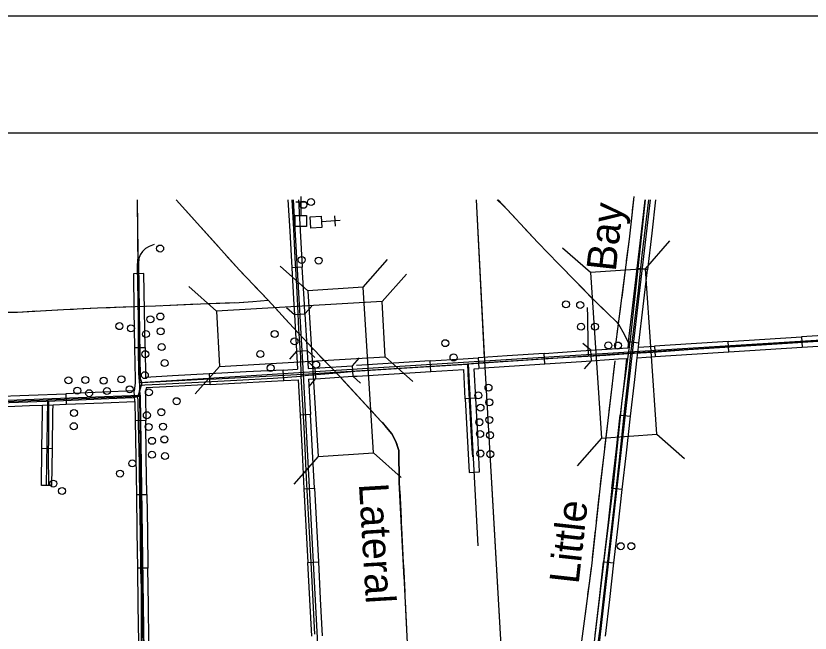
# Model space of a CAD drawing. Extents: x 646058 to 725608, y 1473014 to 1561048.
# Drawn here: x 656968 to 662655, y 1556632 to 1561048 of the extents above; entities that cross this region are included whole.
import ezdxf

# ---------------------------------------------------------------- set-up
doc = ezdxf.new("R2010")
doc.units = 0
for name, color, linetype in [('Default', 7, 'Continuous'), ('R_Border Notes', 7, 'Continuous'), ('T_Vehicle Path Rt', 7, 'Continuous')]:
    doc.layers.add(name, color=color, linetype=linetype)

msp = doc.modelspace()

# ---------------------------------------------------------------- linework, layer by layer
at = {"layer": 'Default'}
for p, q in [((658971.9, 1559717.6), (659046.9, 1559717.6)), ((659009.4, 1559755.1), (659009.4, 1559620.4)), ((659250.2, 1559618.7), (659254.7, 1559543.8)), ((659289.9, 1559583.5), (659155.5, 1559575.4)), ((661477.3, 1559239.6), (661651, 1559438.4)), ((661082.2, 1559213), (660883.4, 1559386.7)), ((659454.8, 1559106.8), (659629.4, 1559304.8)), ((659059.5, 1559082), (658861.6, 1559256.7)), ((661490.9, 1559232.1), (661416.4, 1559240.8)), ((657884.3, 1559204), (657809.4, 1559202.8)), ((659590.2, 1559003.6), (659765.9, 1559200.6)), ((658404.1, 1558936), (658207.1, 1559111.8)), ((659000.3, 1558914.3), (659000.3, 1558914.3)), ((662594.5, 1558752.9), (662599.3, 1558678)), ((661429.7, 1558707.7), (661355.2, 1558716.4)), ((662072.4, 1558644.4), (662067.6, 1558719.2)), ((657817.7, 1558674.9), (657892.7, 1558676.1)), ((659015.3, 1558651.3), (659015.3, 1558651.3)), ((661089.2, 1558580.5), (661084.1, 1558655.4)), ((661417.5, 1558602.6), (661426.3, 1558678.3)), ((661540.7, 1558685.6), (661545.5, 1558610.7)), ((659612.7, 1558608.2), (659809.7, 1558432.5)), ((660486.9, 1558615.2), (660277.5, 1558601.2)), ((660277.5, 1558601.2), (660282.9, 1558528.1)), ((660750.3, 1558632.9), (660486.9, 1558615.2)), ((660755.4, 1558558.1), (660750.3, 1558632.9)), ((661086.7, 1558618), (661086.7, 1558618)), ((658426.6, 1558540.7), (658250.8, 1558343.7)), ((659116.7, 1558452.9), (659112, 1558527.7)), ((659375.8, 1558544.3), (659380.4, 1558469.4)), ((659939.9, 1558504.4), (659935.3, 1558579.3)), ((660282.9, 1558528.1), (660755.4, 1558558.1)), ((658352, 1558486.1), (658356, 1558411.2)), ((658885.6, 1558439.7), (658881.6, 1558514.6)), ((658885.6, 1558439.7), (658881.6, 1558514.6)), ((659114.4, 1558490.3), (659114.4, 1558490.3)), ((659378.1, 1558506.8), (659378.1, 1558506.8)), ((659380.4, 1558469.4), (659413, 1558471.4)), ((657821, 1558289.5), (657816, 1558364.4)), ((657325.8, 1558344.8), (657328.7, 1558269.9)), ((660260.9, 1558313), (660186, 1558309.1)), ((660260.9, 1558313), (660260.9, 1558313)), ((659077.7, 1558195.3), (659002.8, 1558191.3)), ((661295.3, 1558191.7), (661369.8, 1558183.2)), ((657898, 1558152.8), (657823, 1558151.7)), ((657898, 1558152.8), (657898, 1558152.8)), ((661162.1, 1558027.7), (660988.4, 1557828.9)), ((661557.2, 1558054.3), (661756, 1557880.6)), ((657229.3, 1557951.4), (657154.3, 1557952.4)), ((659529, 1557921.1), (659727, 1557746.5)), ((659133.8, 1557896.4), (658959.2, 1557698.4)), ((660214, 1557781.8), (660288.9, 1557785.8)), ((657225.5, 1557687.4), (657150.5, 1557688.5)), ((657830.6, 1557623.8), (657905.6, 1557624.8)), ((659030.9, 1557664.1), (659105.8, 1557668.1)), ((661310.1, 1557658.6), (661235.5, 1557667.1)), ((659059, 1557136.8), (659133.9, 1557140.8)), ((661175.8, 1557142.4), (661250.3, 1557134)), ((657913.2, 1557096.9), (657838.2, 1557095.8))]:
    msp.add_line(p, q, dxfattribs=at)
for points in [[(657836.4, 1559731.1), (657842.5, 1559236.4)], [(657836.4, 1559731.1), (657852.6, 1558422.3), (657853.7, 1558332.9), (657886.7, 1555776.3), (657888, 1555674.8), (657919.2, 1553129.9), (657922.4, 1553034.6), (657948.9, 1552246.6), (657964.6, 1551804.3), (657962.8, 1550661.1), (657966.7, 1550505.3), (657969.3, 1550400.1), (657996.7, 1547841.2)], [(659747.4, 1557022.3), (659713.2, 1557712.2), (659709.8, 1557937.6), (659689.4, 1558003.4), (659660.7, 1558057.1), (659610.9, 1558118.4), (659287.2, 1558467.1), (659093.7, 1558668.3), (658925.1, 1558850.3), (658775.1, 1559014.3), (658568.9, 1559229.6), (658116.7, 1559731.1)], [(658116.7, 1559731.1), (658568.9, 1559229.6), (658775.1, 1559014.3), (658925.1, 1558850.3), (658960.7, 1558811.9)], [(658116.7, 1559731.1), (658248.6, 1559584.7)], [(658916.2, 1559731.1), (658928.8, 1559509.1)], [(658943.6, 1559731.1), (658955.8, 1559523.4), (658964.8, 1559318), (658977, 1559116.8), (658983.6, 1558974.4), (658992.6, 1558806.7), (658998.3, 1558707.7), (659005.7, 1558606.3), (659009.7, 1558471.4)], [(658953.8, 1559731.1), (659024.8, 1558484.7), (659297.5, 1553362.2)], [(658991.3, 1559731.1), (659003.7, 1559513.4)], [(660325.5, 1558577.4), (660267.1, 1559731.1)], [(660324.1, 1558604.2), (660267.1, 1559731.1)], [(660415.4, 1559732.9), (660456.1, 1559693.5), (660485.1, 1559662.6)], [(660420.7, 1559731.1), (660552.8, 1559590.4)], [(661362.2, 1558694.1), (661326.9, 1558769.8), (661286.1, 1558839.1), (661266.3, 1558862), (661206.8, 1558918.4), (661104.1, 1559018), (660852.8, 1559275), (660705.5, 1559427.9), (660420.7, 1559731.1)], [(660420.7, 1559731.1), (660705.5, 1559427.9), (660852.8, 1559275), (661104.1, 1559018), (661206.8, 1558918.4), (661266.3, 1558862), (661281.8, 1558844)], [(661474.1, 1559731.1), (661439.7, 1559417.2), (661367.6, 1558733.9), (661308.2, 1558296.7), (661244.5, 1557694.1), (661185.1, 1557210.2), (661113, 1556611.8), (661049.3, 1556047.3), (660956, 1555266.4), (660896.6, 1554791), (660837.2, 1554315.6), (660809.9, 1554053.3), (660737.8, 1553429.4)], [(660803.4, 1553465), (661080.3, 1555972.4), (661383.8, 1558638), (661511.3, 1559731.1)], [(661389.7, 1559731.1), (661358.7, 1559451.8), (661281.8, 1558844), (661259.4, 1558679)], [(661389.7, 1559731.1), (661370.5, 1559558.1)], [(661372.2, 1558630.2), (661425.7, 1559084.1), (661452.5, 1559336.4), (661501.3, 1559731.1)], [(661392.3, 1559754.9), (661381.4, 1559656.5)], [(661446.9, 1559503), (661473.5, 1559731.1)], [(661549, 1559731.1), (661521.4, 1559494.3)], [(658292.8, 1559535.7), (658425.4, 1559388.7)], [(658928.8, 1559509.1), (658943.9, 1559245.5)], [(659003.7, 1559513.4), (659018.7, 1559249.8)], [(660598, 1559542.3), (660705.5, 1559427.9), (660734, 1559398.3)], [(661363.2, 1559492.5), (661358.7, 1559451.8), (661339, 1559296)], [(661416.4, 1559240.8), (661446.9, 1559503)], [(661521.4, 1559494.3), (661490.9, 1559232.1)], [(655610.5, 1559406.1), (655874.5, 1559357.8), (655954, 1559335.1), (655978.1, 1559325.2), (655995.1, 1559276.9), (656032, 1559248.5), (656091.6, 1559211.6), (656293.1, 1559116.5), (656515.9, 1559014.3), (656616.7, 1558971.8), (656707.5, 1558937.7), (656750.1, 1558926.3), (656792.6, 1558927.8), (656978.5, 1558929.2), (657309.2, 1558947.6), (657553.2, 1558959), (657821.5, 1558968.9), (657967.6, 1558973.2), (658291.2, 1558988.8), (658566.5, 1558998.7), (658665.8, 1559004.4), (658775.1, 1559014.3)], [(657958.2, 1559412.7), (657923, 1559397.8), (657897.3, 1559383.2), (657874.8, 1559362.2), (657858.8, 1559337.7), (657849.4, 1559313.4), (657845.7, 1559274.7), (657858.7, 1558454.5), (657870.9, 1558422.7), (657854.2, 1558362.1), (657858, 1558328.5), (657886.7, 1556334.8)], [(658469.6, 1559339.6), (658568.9, 1559229.6), (658603.3, 1559193.6)], [(660779.7, 1559350.8), (660852.8, 1559275), (660917.6, 1559208.7)], [(657838.5, 1559307.9), (657837.4, 1559249.4), (657841.8, 1559022.9), (657842.8, 1558862.6), (657843.9, 1558666.4), (657845, 1558492), (657853.7, 1558403.1), (657853.7, 1558378.2), (657849.3, 1558347.8), (657839.5, 1558321.5)], [(661330.7, 1559230.5), (661305.9, 1559034.1)], [(661385.8, 1558978.6), (661416.4, 1559240.8)], [(661460.3, 1558969.9), (661490.9, 1559232.1)], [(657809.4, 1559202.8), (657813.5, 1558938.9)], [(657888.5, 1558940), (657884.3, 1559204)], [(660963.8, 1559161.5), (661102.2, 1559020)], [(656267.6, 1559128.6), (656293.1, 1559116.5), (656515.9, 1559014.3), (656616.7, 1558971.8), (656707.5, 1558937.7), (656750.1, 1558926.3), (656792.6, 1558927.8), (656978.5, 1558929.2), (657309.2, 1558947.6), (657553.2, 1558959), (657795.9, 1558968)], [(658649, 1559146), (658775.1, 1559014.3), (658785.7, 1559002.7)], [(657906.4, 1558971.4), (657967.6, 1558973.2), (658291.2, 1558988.8), (658566.5, 1558998.7), (658665.8, 1559004.4), (658775.1, 1559014.3)], [(658071.3, 1558978.2), (658269.1, 1558987.7)], [(658335, 1558990.4), (658532.9, 1558997.5)], [(658598.8, 1559000.6), (658665.8, 1559004.4), (658775.1, 1559014.3)], [(661355.2, 1558716.4), (661385.8, 1558978.6)], [(656919.3, 1558928.7), (656978.5, 1558929.2), (657117.1, 1558936.9)], [(657183, 1558940.6), (657309.2, 1558947.6), (657380.7, 1558951)], [(657446.6, 1558954), (657553.2, 1558959), (657644.4, 1558962.4)], [(657710.4, 1558964.8), (657795.9, 1558968)], [(657813.5, 1558938.9), (657817.7, 1558674.9)], [(657892.7, 1558676.1), (657888.5, 1558940)], [(657906.4, 1558971.4), (657967.6, 1558973.2), (658005.4, 1558975)], [(658830.2, 1558954), (658897.1, 1558881)], [(658906.9, 1558962.1), (658962.8, 1558912.2)], [(659037.7, 1558916.4), (659087.6, 1558972.4)], [(660279.4, 1557256.5), (660210.3, 1558559), (661383.8, 1558638), (662974.2, 1558739.5), (665600.1, 1558923.2)], [(661058.3, 1558961.7), (661060.8, 1558897.3), (661064.5, 1558694.9), (661067, 1558612.5)], [(661149.5, 1558974), (661206.8, 1558918.4), (661266.3, 1558862), (661281.8, 1558844)], [(661297.6, 1558968.6), (661281.8, 1558844), (661272.1, 1558772.2)], [(661429.7, 1558707.7), (661460.3, 1558969.9)], [(658897.1, 1558881), (658925.1, 1558850.3), (658960.7, 1558811.9)], [(658962.8, 1558912.2), (658985.2, 1558520.1)], [(659037.7, 1558916.4), (659060, 1558524.5)], [(665577.9, 1558917.3), (665352.8, 1558904.3), (664932.4, 1558879.5), (664740.8, 1558865.9), (664271, 1558824.5), (664067, 1558807.2), (663631.8, 1558777.5), (663510.6, 1558770.1), (663208.3, 1558750.3), (662961.7, 1558733.6), (662787.4, 1558723.1), (662493.7, 1558703.9), (662006, 1558673), (661781.6, 1558658.2), (661529.4, 1558640.3), (661352.6, 1558629.8), (661193.7, 1558618.6), (661063.3, 1558610.6), (660798.7, 1558595.7), (660555.2, 1558579.1), (660314.7, 1558564.8), (660202.2, 1558556.2)], [(662331.1, 1558736), (662594.5, 1558752.9)], [(662858, 1558769.7), (662594.5, 1558752.9)], [(659213.8, 1558543.3), (659093.7, 1558668.3), (659054.6, 1558710.5)], [(659099.5, 1558662.3), (659093.7, 1558668.3), (659054.6, 1558710.5)], [(662966.5, 1558742.1), (660325.5, 1558577.4)], [(661084.1, 1558655.4), (661027.7, 1558704.7)], [(661355.2, 1558716.4), (661350.2, 1558673.3)], [(661426.3, 1558678.3), (661429.7, 1558707.7)], [(661804.2, 1558702.4), (661540.7, 1558685.6)], [(662067.6, 1558719.2), (661804.2, 1558702.4)], [(662067.6, 1558719.2), (662331.1, 1558736)], [(662599.3, 1558678), (662862.8, 1558694.8)], [(657817.7, 1558674.9), (657821.3, 1558447.3), (657822.2, 1558421.1)], [(657892.7, 1558676.1), (657896.1, 1558461.6)], [(658977.8, 1558649.2), (658927.9, 1558593.2)], [(658977.8, 1558649.2), (659052.7, 1558653.4)], [(659108.7, 1558603.5), (659052.7, 1558653.4)], [(660750.3, 1558632.9), (661013.7, 1558650.6)], [(661013.7, 1558650.6), (661277.1, 1558668.4)], [(661277.1, 1558668.4), (661350.2, 1558673.3)], [(661426.3, 1558678.3), (661540.7, 1558685.6)], [(661808.9, 1558627.5), (662072.4, 1558644.4)], [(662072.4, 1558644.4), (662335.9, 1558661.2)], [(662335.9, 1558661.2), (662599.3, 1558678)], [(659213.8, 1558543.3), (659145.2, 1558614.7)], [(659425.4, 1558600.5), (659375.8, 1558544.3)], [(659935.3, 1558579.3), (660170.9, 1558594.1), (660277.5, 1558601.2)], [(660830.5, 1553984.9), (660865.7, 1554286.1), (660902.5, 1554601.2), (660927.1, 1554815.2), (660989.2, 1555288.6), (661021.8, 1555570.5), (661068, 1555972.4), (661117.1, 1556398.1), (661151.1, 1556664.1), (661188.7, 1556982.2), (661216.2, 1557225.8), (661259.5, 1557598), (661287, 1557848.1), (661328.2, 1558239.9), (661359.2, 1558512.4), (661372.2, 1558630.2)], [(661018.8, 1558575.8), (661282.2, 1558593.5)], [(661039.8, 1558524.1), (661089.2, 1558580.5)], [(661282.2, 1558593.5), (661341.5, 1558597.5)], [(661341.5, 1558597.5), (661325.1, 1558454)], [(661399.7, 1558445.5), (661417.5, 1558602.6)], [(661417.5, 1558602.6), (661545.5, 1558610.7)], [(661545.5, 1558610.7), (661808.9, 1558627.5)], [(660325.5, 1558577.4), (657852.6, 1558422.3)], [(658356.4, 1558448.8), (659024.8, 1558484.7), (660210.3, 1558559)], [(659015.5, 1558471.9), (659064.3, 1558476.8), (659267.2, 1558495), (659395.8, 1558506.3), (659767.1, 1558529.3), (660202.2, 1558556.2)], [(659112, 1558527.7), (659055.8, 1558577.3)], [(659060, 1558524.5), (659144.8, 1558529.8)], [(659144.8, 1558529.8), (659375.8, 1558544.3)], [(659671.8, 1558562.8), (659408.3, 1558546.3)], [(659935.3, 1558579.3), (659671.8, 1558562.8)], [(660202.2, 1558556.2), (660206.5, 1558435), (660233.1, 1557953.3), (660237.4, 1557893.6)], [(660249.7, 1558524), (660283, 1558526.1)], [(660260.9, 1558313), (660249.7, 1558524)], [(660478.2, 1555921.9), (660325.5, 1558577.4)], [(661255.9, 1558579.7), (661149.5, 1557665.2), (661089.3, 1557112.2), (660975.9, 1556250.8), (660951, 1555956.5), (660877.8, 1555340.5), (660749, 1554042.3), (660702.9, 1553393.6)], [(660755.4, 1558558.1), (661018.8, 1558575.8)], [(661255.9, 1558579.7), (661244.4, 1558481.4)], [(657853.7, 1558403.1), (657890.5, 1558408.5), (657995.6, 1558412.9), (658414.9, 1558434.5), (658549.2, 1558442.1), (658811.4, 1558456.2), (658913.3, 1558463.8), (659009.7, 1558471.4)], [(658088.4, 1558471.9), (657896.1, 1558461.6)], [(658352, 1558486.1), (658088.4, 1558471.9)], [(658618, 1558500.4), (658354.3, 1558486.2)], [(658881.6, 1558514.6), (658618, 1558500.4)], [(658881.6, 1558514.6), (658985.2, 1558520.1)], [(659009.7, 1558471.4), (659032.4, 1558059.6), (659047.6, 1557741), (659076.9, 1557181.8), (659089.9, 1556955.3), (659107.2, 1556624.8)], [(659149.5, 1558454.9), (659380.4, 1558469.4)], [(659380.4, 1558469.4), (659436.7, 1558419.8)], [(659413, 1558471.4), (659676.5, 1558487.9)], [(659676.5, 1558487.9), (659939.9, 1558504.4)], [(659939.9, 1558504.4), (660174.9, 1558519.2)], [(660186, 1558309.1), (660174.9, 1558519.2)], [(657822.2, 1558421.1), (657816, 1558364.4)], [(658354, 1558448.6), (657870.9, 1558422.7)], [(658356, 1558411.2), (658092.4, 1558397)], [(658358.4, 1558411.3), (658622, 1558425.5)], [(658622, 1558425.5), (658885.6, 1558439.7)], [(658885.6, 1558439.7), (658989.3, 1558445.2)], [(658989.3, 1558445.2), (659002.8, 1558191.3)], [(659064.2, 1558449.6), (659149.5, 1558454.9)], [(659064.2, 1558449.6), (659077.7, 1558195.3)], [(659067.1, 1558396.6), (659116.7, 1558452.9)], [(659298.3, 1558455.1), (659610.9, 1558118.4), (659660.7, 1558057.1), (659689.4, 1558003.4), (659709.8, 1557937.6), (659713.2, 1557712.2), (659803.4, 1555890)], [(659298.3, 1558455.1), (659365.6, 1558382.6)], [(661236.8, 1558415.8), (661213.9, 1558219.2)], [(661325.1, 1558454), (661295.3, 1558191.7)], [(661369.8, 1558183.2), (661399.7, 1558445.5)], [(657589.5, 1558355.3), (657325.8, 1558344.8)], [(657816, 1558364.4), (657589.5, 1558355.3)], [(657899.9, 1558386.7), (657895.7, 1558358.4), (657895.4, 1558330.8), (657898, 1558152.8)], [(658092.4, 1558397), (657899.9, 1558386.7)], [(657853.7, 1558332.9), (655214.5, 1558232.7)], [(655216.8, 1558228.4), (655389.7, 1558230.1), (657858, 1558328.5)], [(657839.5, 1558321.5), (657807.1, 1558316.3), (657633.7, 1558307.2), (657309.5, 1558293.6), (657185.1, 1558288.3), (656785.5, 1558275.5), (656545, 1558266.5), (656344.4, 1558259.7), (656177.8, 1558253.7), (655978, 1558243.9), (655832.5, 1558238.6), (655641.8, 1558231.8), (655491.7, 1558226.5), (655417.8, 1558223.5), (655381.7, 1558221.2), (655320.6, 1558218.2), (655288.5, 1558218.4)], [(656798.2, 1558323.8), (657062, 1558334.3)], [(657062, 1558334.3), (657325.8, 1558344.8)], [(657188, 1557687.9), (657196.9, 1558299.7)], [(657871.2, 1556330.8), (657867.4, 1556616.5), (657867.4, 1556775.6), (657867.4, 1556951.3), (657863.6, 1557090.1), (657859.9, 1557343.5), (657856.1, 1557581.8), (657853.1, 1557835.9), (657851.6, 1557945.2), (657847, 1558131.5), (657844.8, 1558301.9), (657839.5, 1558321.5)], [(659410.5, 1558334.2), (659545.2, 1558189.1)], [(660186, 1558309.1), (660200, 1558045.4)], [(660274.9, 1558049.4), (660260.9, 1558313)], [(656801.2, 1558248.8), (657064.9, 1558259.4)], [(657064.9, 1558259.4), (657158.8, 1558263.1)], [(657158.2, 1558216.4), (657158.8, 1558263.1)], [(657158.8, 1558263.1), (657233.9, 1558266.1), (657328.7, 1558269.9)], [(657200.5, 1558289), (657201.8, 1558081.9), (657200, 1557865.7), (657201.2, 1557740.2), (657200.6, 1557687.3)], [(657233.2, 1558215.3), (657233.9, 1558266.1)], [(657328.7, 1558269.9), (657592.5, 1558280.4)], [(657592.5, 1558280.4), (657821, 1558289.5)], [(657821, 1558289.5), (657823, 1558151.7)], [(657154.3, 1557952.4), (657158.2, 1558216.4)], [(657229.3, 1557951.4), (657233.2, 1558215.3)], [(659002.8, 1558191.3), (659016.9, 1557927.7)], [(659091.8, 1557931.7), (659077.7, 1558195.3)], [(661265.4, 1557929.4), (661295.3, 1558191.7)], [(661339.9, 1557920.9), (661369.8, 1558183.2)], [(657823, 1558151.7), (657826.8, 1557887.7)], [(657901.8, 1557888.8), (657898, 1558152.8)], [(659590.1, 1558140.7), (659610.9, 1558118.4), (659660.7, 1558057.1), (659689.4, 1558003.4), (659697.6, 1557977)], [(661206.3, 1558153.6), (661183.5, 1557956.9)], [(660200, 1558045.4), (660214, 1557781.8)], [(660288.9, 1557785.8), (660274.9, 1558049.4)], [(657150.5, 1557688.5), (657154.3, 1557952.4)], [(657225.5, 1557687.4), (657229.3, 1557951.4)], [(659016.9, 1557927.7), (659030.9, 1557664.1)], [(659105.8, 1557668.1), (659091.8, 1557931.7)], [(659710.2, 1557912.9), (659713.2, 1557714.9)], [(661235.5, 1557667.1), (661265.4, 1557929.4)], [(661310.1, 1557658.6), (661339.9, 1557920.9)], [(657826.8, 1557887.7), (657830.6, 1557623.8)], [(657905.6, 1557624.8), (657901.8, 1557888.8)], [(661175.8, 1557891.4), (661153, 1557694.7)], [(660478.2, 1555921.9), (660370.7, 1557790.5)], [(657830.6, 1557623.8), (657834.4, 1557359.8)], [(657905.6, 1557624.8), (657909.4, 1557360.9)], [(659030.9, 1557664.1), (659044.9, 1557400.5)], [(659105.8, 1557668.1), (659119.8, 1557404.4)], [(659716.4, 1557649), (659726.2, 1557451.2)], [(661145.6, 1557629.1), (661124.2, 1557432.3)], [(661235.5, 1557667.1), (661205.7, 1557404.7)], [(661280.2, 1557396.3), (661310.1, 1557658.6)], [(659044.9, 1557400.5), (659059, 1557136.8)], [(659119.8, 1557404.4), (659133.9, 1557140.8)], [(661205.7, 1557404.7), (661175.8, 1557142.4)], [(661250.3, 1557134), (661280.2, 1557396.3)], [(657834.4, 1557359.8), (657838.2, 1557095.8)], [(657909.4, 1557360.9), (657913.2, 1557096.9)], [(659729.4, 1557385.3), (659739.2, 1557187.5)], [(661117, 1557366.7), (661095.6, 1557169.8)], [(659073, 1556873.2), (659059, 1557136.8)], [(659133.9, 1557140.8), (659147.9, 1556877.2)], [(659742.5, 1557121.6), (659747.4, 1557022.7)], [(661088.2, 1557104.2), (661075.3, 1557006.1)], [(661146, 1556880.1), (661175.8, 1557142.4)], [(661220.5, 1556871.7), (661250.3, 1557134)], [(657838.2, 1557095.8), (657842, 1556831.8)], [(657917, 1556832.9), (657913.2, 1557096.9)], [(659747.4, 1557022.7), (659752.3, 1556923.9)], [(661075.3, 1557006.1), (661062.4, 1556907.9)], [(659147.9, 1556877.2), (659161.9, 1556613.6)], [(661116.1, 1556617.8), (661146, 1556880.1)], [(657842, 1556831.8), (657845.8, 1556567.9)], [(657920.8, 1556569), (657917, 1556832.9)], [(659087, 1556609.6), (659073, 1556873.2)], [(659755.5, 1556857.9), (659765.3, 1556660.2)], [(661053.8, 1556842.5), (661027.9, 1556646.2)], [(661190.6, 1556609.3), (661220.5, 1556871.7)]]:
    msp.add_lwpolyline(points, dxfattribs=at)
for points in [[(658968.8, 1559542.4), (658968.8, 1559620.4), (659049.7, 1559620.4), (659049.7, 1559542.4)], [(659075.2, 1559611.1), (659153, 1559615.9), (659157.9, 1559535.1), (659080.1, 1559530.4)], [(658943.9, 1559245.5), (658958.9, 1558982), (658962.8, 1558912.2), (659037.7, 1558916.4), (659033.7, 1558986.2), (659018.7, 1559249.8), (658943.9, 1559245.5)], [(661082.2, 1559213), (661162.1, 1558027.7), (661557.2, 1558054.3), (661477.3, 1559239.6)], [(659059.5, 1559082), (659133.8, 1557896.4), (659529, 1557921.1), (659454.8, 1559106.8)], [(659590.2, 1559003.6), (658404.1, 1558936), (658426.6, 1558540.7), (659612.7, 1558608.2)]]:
    msp.add_lwpolyline(points, close=True, dxfattribs=at)
for centre in [(659026.9, 1559696.8), (659081.9, 1559716.4), (658001, 1559383.8), (658001, 1559383.8), (659015.2, 1559302.4), (659136.1, 1559297.2), (660906.6, 1558984.4), (661008.8, 1558979), (658002.4, 1558897.4), (657931.7, 1558877.7), (657709.5, 1558828.4), (657791.9, 1558812.7), (658005.2, 1558791.2), (661015.5, 1558824.1), (661114.3, 1558824.7), (657899.2, 1558771.5), (658821.1, 1558772.1), (658012.3, 1558678.7), (658963.1, 1558719.5), (660042.9, 1558706.6), (661211.1, 1558690.2), (661279, 1558689.7), (657894.5, 1558627.7), (658718.3, 1558628.7), (658032.9, 1558564), (660102, 1558604.4), (658791.9, 1558528.8), (659118, 1558552.6), (657344.7, 1558441.4), (657465.2, 1558442.9), (657724.1, 1558447.3), (657891.5, 1558477.6), (657596.5, 1558438.4), (660352.3, 1558388.6), (657407.5, 1558366.8), (657492.7, 1558348.7), (657620.1, 1558363.8), (657783, 1558376.6), (657920.2, 1558355.5), (660278.8, 1558332.8), (658119.2, 1558291.3), (660359, 1558283.3), (660294.9, 1558244.4), (657384.1, 1558206.9), (657905.9, 1558191.1), (658008.9, 1558212.6), (660358.4, 1558157.2), (657382.9, 1558112.4), (657918.7, 1558107.4), (658021.7, 1558109.8), (660287.5, 1558141.2), (660292.4, 1558057.3), (660363.4, 1558048.2), (657942.8, 1558007.8), (658031.5, 1558017.4), (657942, 1557908.3), (658035.5, 1557898.7), (660294.3, 1557917), (660365.2, 1557912.4), (657801.8, 1557846.4), (657714.4, 1557773.4), (657235.7, 1557701.5), (657298.8, 1557648.9), (661299.3, 1557254), (661374.5, 1557254)]:
    msp.add_circle(centre, 25, dxfattribs=at)
at = {"layer": 'R_Border Notes'}
msp.add_line((648725.4, 1560211), (716704.1, 1560211), dxfattribs=at)
at = {"layer": 'T_Vehicle Path Rt'}
msp.add_line((646059.2, 1561048.3), (717725.9, 1561048.3), dxfattribs=at)
msp.add_lwpolyline([(646057.8, 1561048.3), (717725.9, 1561048.3), (717725.9, 1515180.7), (646057.8, 1515180.7)], close=True, dxfattribs=at)

# ---------------------------------------------------------------- texts
at = {"layer": 'Default'}
for s, rotation, p in [('Bay', 83.6847, (661262.9, 1559214.8)), ('Lateral', 273.4166, (659424, 1557699.7)), ('Little', 83.6439, (660997.5, 1556978.2))]:
    msp.add_text(s, height=211.2, rotation=rotation, dxfattribs=at).set_placement(p)

doc.saveas('drawing.dxf')
